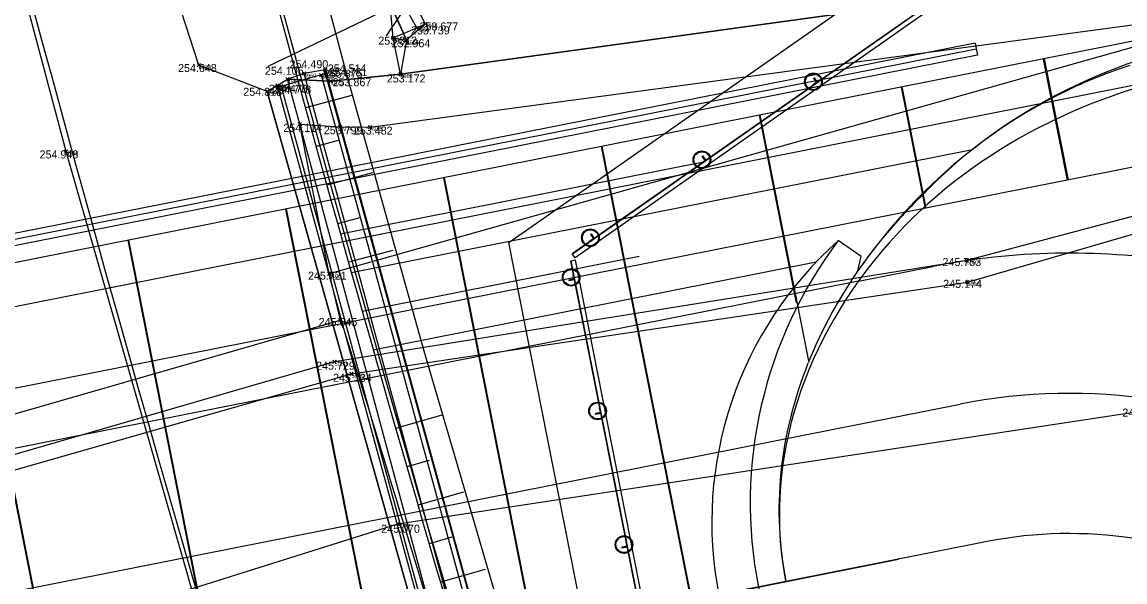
# Model space of a CAD drawing. Extents: x -809973 to -809318, y -1011363 to -1010505.
# Drawn here: x -809841.74 to -809827.96, y -1010985.79 to -1010978.8 of the extents above; entities that cross this region are included whole.
import ezdxf

# ---------------------------------------------------------------- set-up
doc = ezdxf.new("R2010")
doc.units = 0
for name, color, linetype in [('18b - zaměření - čísla bodů', 7, 'Continuous'), ('18c - zaměření - výšky', 7, 'Continuous'), ('Návrh', 7, 'Continuous'), ('SO04 - Železniční spodek', 7, 'Continuous'), ('SO_01', 7, 'Continuous'), ('stav_stav', 7, 'Continuous')]:
    doc.layers.add(name, color=color, linetype=linetype)

# ---------------------------------------------------------------- blocks, each defined once
blk = doc.blocks.new('POINT_DISPLAY')
for p, q in [((-0.021, -0.021), (0.021, 0.021)), ((-0.021, 0.021), (0.021, -0.021))]:
    blk.add_line(p, q)

msp = doc.modelspace()

# ---------------------------------------------------------------- linework, layer by layer
at = {"layer": 'Návrh'}
msp.add_arc((-809483.868, -1010882.207), 370.5, 195.00213, 204.78693, dxfattribs=at)
at = {"layer": 'SO04 - Železniční spodek'}
for points in [[(-809844.502, -1010948.259), (-809843.86, -1010951.753), (-809843.202, -1010955.243), (-809842.522, -1010958.729), (-809841.813, -1010962.21), (-809841.069, -1010965.683), (-809840.285, -1010969.148), (-809839.459, -1010972.604), (-809838.59, -1010976.05), (-809837.678, -1010979.484), (-809836.721, -1010982.905), (-809835.72, -1010986.314), (-809834.673, -1010989.708), (-809833.585, -1010993.088), (-809832.46, -1010996.457), (-809831.306, -1010999.816), (-809830.127, -1011003.167), (-809828.93, -1011006.512), (-809827.721, -1011009.854), (-809826.507, -1011013.193)], [(-809837.621, -1010979.718), (-809838.2, -1010979.874)], [(-809837.79, -1010980.282), (-809838.066, -1010980.356)], [(-809837.364, -1010980.685), (-809837.933, -1010980.837)], [(-809837.522, -1010981.245), (-809837.798, -1010981.319)], [(-809837.107, -1010981.651), (-809837.663, -1010981.8)], [(-809836.497, -1010983.709), (-809837.073, -1010983.873)], [(-809836.654, -1010984.273), (-809836.934, -1010984.353)], [(-809836.225, -1010984.671), (-809836.795, -1010984.833)], [(-809836.371, -1010985.233), (-809836.655, -1010985.313)], [(-809835.954, -1010985.634), (-809836.514, -1010985.793)]]:
    msp.add_lwpolyline(points, dxfattribs=at)
for centre, radius, start, end in [((-809453.305, -1010872.818), 406.4, 193.63597, 201.43276), ((-809483.922, -1010882.181), 367.5, 195.00277, 200.92799), ((-809524.411, -1010895.31), 331.2, 194.62152, 202.36706)]:
    msp.add_arc(centre, radius, start, end, dxfattribs=at)
at = {"layer": 'SO_01'}
for p, q in [((-809828.802, -1010977.453), (-809834.866, -1010981.695)), ((-809828.8, -1010977.457), (-809834.863, -1010981.699)), ((-809828.768, -1010977.502), (-809834.832, -1010981.744)), ((-809827.206, -1010978.912), (-809853.624, -1010984.137)), ((-809829.834, -1010979.065), (-809852.149, -1010983.48)), ((-809829.819, -1010979.139), (-809852.135, -1010983.553)), ((-809829.834, -1010979.065), (-809829.804, -1010979.213)), ((-809829.804, -1010979.213), (-809852.12, -1010983.627)), ((-809828.982, -1010979.263), (-809828.683, -1010980.774)), ((-809828.972, -1010979.261), (-809828.673, -1010980.772)), ((-809827.101, -1010979.442), (-809853.52, -1010984.667)), ((-809830.757, -1010979.614), (-809830.459, -1010981.125)), ((-809830.748, -1010979.612), (-809830.449, -1010981.123)), ((-809832.533, -1010979.965), (-809832.07, -1010982.305)), ((-809832.523, -1010979.964), (-809831.912, -1010983.053)), ((-809837.627, -1010981.926), (-809829.865, -1010980.391)), ((-809834.505, -1010980.356), (-809832.262, -1010991.694)), ((-809834.495, -1010980.354), (-809832.252, -1010991.692)), ((-809826.907, -1010980.423), (-809853.326, -1010985.648)), ((-809837.763, -1010981.443), (-809833.207, -1010980.542)), ((-809836.477, -1010980.746), (-809834.234, -1010992.084)), ((-809836.467, -1010980.744), (-809834.224, -1010992.082)), ((-809838.448, -1010981.136), (-809836.206, -1010992.474)), ((-809838.439, -1010981.134), (-809836.196, -1010992.472)), ((-809840.42, -1010981.526), (-809838.178, -1010992.864)), ((-809840.41, -1010981.524), (-809838.168, -1010992.862)), ((-809837.491, -1010982.409), (-809834.031, -1010981.724)), ((-809834.826, -1010981.774), (-809834.885, -1010981.785)), ((-809833.153, -1010990.515), (-809834.88, -1010981.784)), ((-809834.832, -1010981.744), (-809834.866, -1010981.695)), ((-809833.099, -1010990.504), (-809834.826, -1010981.774)), ((-809842.392, -1010981.916), (-809840.149, -1010993.254)), ((-809842.382, -1010981.914), (-809840.14, -1010993.252)), ((-809837.354, -1010982.891), (-809831.819, -1010981.796)), ((-809833.158, -1010990.516), (-809834.885, -1010981.785)), ((-809831.291, -1010982.037), (-809848.657, -1010985.472)), ((-809830.791, -1010985.512), (-809846.92, -1010988.702)), ((-809832.198, -1010985.784), (-809846.393, -1010988.591))]:
    msp.add_line(p, q, dxfattribs=at)
for points in [[(-809835.659, -1010981.554), (-809829.119, -1010976.981), (-809826.574, -1010976.477), (-809826.434, -1010978.736)], [(-809831.806, -1010979.554), (-809831.863, -1010979.594), (-809831.864, -1010979.592)], [(-809831.863, -1010979.586), (-809831.823, -1010979.558)], [(-809831.82, -1010979.545), (-809831.849, -1010979.504)], [(-809831.848, -1010979.498), (-809831.846, -1010979.497), (-809831.806, -1010979.554)], [(-809833.199, -1010980.529), (-809833.256, -1010980.569), (-809833.257, -1010980.567)], [(-809833.256, -1010980.56), (-809833.216, -1010980.532)], [(-809833.213, -1010980.519), (-809833.242, -1010980.479)], [(-809833.241, -1010980.473), (-809833.239, -1010980.471), (-809833.199, -1010980.529)], [(-809834.592, -1010981.503), (-809834.649, -1010981.543), (-809834.65, -1010981.541)], [(-809834.649, -1010981.535), (-809834.609, -1010981.506)], [(-809834.606, -1010981.494), (-809834.635, -1010981.453)], [(-809834.634, -1010981.447), (-809834.632, -1010981.446), (-809834.592, -1010981.503)], [(-809824.741, -1010990.164), (-809824.472, -1010992.461), (-809826.009, -1010992.763), (-809833.786, -1010991.025), (-809835.659, -1010981.554)], [(-809831.298, -1010981.906), (-809831.257, -1010981.729), (-809831.544, -1010981.53)], [(-809831.291, -1010982.037), (-809830.362, -1010981.853)], [(-809834.908, -1010982.027), (-809834.908, -1010982.029), (-809834.839, -1010982.016)], [(-809834.856, -1010982.012), (-809834.905, -1010982.022)], [(-809834.859, -1010981.953), (-809834.849, -1010982.001)], [(-809834.839, -1010982.016), (-809834.853, -1010981.947), (-809834.855, -1010981.948)], [(-809854.161, -1010988.344), (-809830.022, -1010983.57)], [(-809834.578, -1010983.695), (-809834.578, -1010983.697), (-809834.509, -1010983.684)], [(-809834.526, -1010983.68), (-809834.575, -1010983.689)], [(-809834.529, -1010983.621), (-809834.519, -1010983.669)], [(-809834.509, -1010983.684), (-809834.523, -1010983.615), (-809834.525, -1010983.615)], [(-809834.248, -1010985.362), (-809834.248, -1010985.365), (-809834.179, -1010985.351)], [(-809834.196, -1010985.347), (-809834.245, -1010985.357)], [(-809834.199, -1010985.288), (-809834.189, -1010985.337)], [(-809834.179, -1010985.351), (-809834.193, -1010985.283), (-809834.195, -1010985.283)], [(-809829.683, -1010985.286), (-809832.198, -1010985.784)]]:
    msp.add_lwpolyline(points, dxfattribs=at)
for centre, radius in [((-809831.854, -1010979.546), 0.11), ((-809831.854, -1010979.546), 0.1), ((-809833.247, -1010980.52), 0.11), ((-809833.247, -1010980.52), 0.1), ((-809834.64, -1010981.494), 0.11), ((-809834.64, -1010981.494), 0.1), ((-809834.88, -1010981.988), 0.11), ((-809834.88, -1010981.988), 0.1), ((-809834.55, -1010983.656), 0.11), ((-809834.55, -1010983.656), 0.1), ((-809834.22, -1010985.324), 0.11), ((-809834.22, -1010985.324), 0.1)]:
    msp.add_circle(centre, radius, dxfattribs=at)
for centre, radius, start, end in [((-809483.868, -1010882.207), 367.5, 195.00213, 200.05975), ((-809483.868, -1010882.207), 373.7, 195.00213, 199.87467), ((-809825.612, -1010985.836), 6.911, 103.0166, 145.3525), ((-809831.845, -1010979.502), 0.0045, 124.9748, 214.9749), ((-809831.828, -1010979.55), 0.009, 304.9748, 34.9749), ((-809831.861, -1010979.59), 0.0045, 124.9748, 214.9749), ((-809833.238, -1010980.476), 0.0045, 124.9748, 214.9749), ((-809833.221, -1010980.525), 0.009, 304.9748, 34.9749), ((-809833.254, -1010980.564), 0.0045, 124.9748, 214.9749), ((-809834.631, -1010981.451), 0.0045, 124.9748, 214.9749), ((-809834.614, -1010981.499), 0.009, 304.9748, 34.9749), ((-809834.647, -1010981.539), 0.0045, 124.9748, 214.9749), ((-809828.427, -1010985.044), 4.696, 131.5786, 250.7932), ((-809827.218, -1010984.804), 5.425, 142.8795, 239.4973), ((-809828.664, -1010990.436), 8.75, 81.0586, 101.1885), ((-809834.904, -1010982.026), 0.0045, 101.1885, 191.1886), ((-809834.854, -1010981.952), 0.0045, 101.1885, 191.1886), ((-809834.858, -1010982.003), 0.009, 281.1885, 11.1886), ((-809828.664, -1010990.436), 7, 81.0586, 101.1885), ((-809834.574, -1010983.694), 0.0045, 101.1885, 191.1886), ((-809834.524, -1010983.62), 0.0045, 101.1885, 191.1886), ((-809834.528, -1010983.671), 0.009, 281.1885, 11.1886), ((-809828.664, -1010990.436), 5.25, 81.0586, 101.1885), ((-809834.244, -1010985.361), 0.0045, 101.1885, 191.1886), ((-809834.194, -1010985.287), 0.0045, 101.1885, 191.1886), ((-809834.198, -1010985.339), 0.009, 281.1885, 11.1886)]:
    msp.add_arc(centre, radius, start, end, dxfattribs=at)
for centre, major_axis, ratio, start_param, end_param in [((-809826.127, -1010984.193), (-5.947, -1.176), 0.8, 4.717975, 5.497787), ((-809826.13, -1010984.193), (-5.722, -1.132), 0.882873, 4.848896, 5.031621), ((-809826.13, -1010984.193), (-5.722, -1.132), 0.882873, 5.033427, 5.386405), ((-809825.759, -1010984.12), (-6.315, -1.249), 0.8, 5.388601, 5.497787), ((-809825.207, -1010984.407), (-6.99, -1.383), 0.8, 5.497787, 5.801717), ((-809825.575, -1010984.48), (-6.622, -1.31), 0.8, 5.497787, 6.283185), ((-809825.207, -1010984.408), (-6.99, -1.383), 0.800068, 5.804756, 6.283146)]:
    msp.add_ellipse(centre, major_axis=major_axis, ratio=ratio, start_param=start_param, end_param=end_param, dxfattribs=at)
at = {"layer": 'stav_stav'}
for p, q in [((-809841.189, -1010980.417), (-809842.723, -1010974.633)), ((-809836.936, -1010979.029), (-809838.163, -1010976.258)), ((-809838.163, -1010976.258), (-809836.936, -1010979.029)), ((-809836.702, -1010978.825), (-809837.958, -1010976.205)), ((-809839.533, -1010979.34), (-809840.375, -1010976.742)), ((-809825.985, -1010977.935), (-809837.013, -1010979.451)), ((-809837.013, -1010979.451), (-809825.985, -1010977.935)), ((-809837.103, -1010978.997), (-809837.176, -1010978.22)), ((-809836.807, -1010978.875), (-809837.176, -1010978.22)), ((-809837.103, -1010978.997), (-809837.176, -1010978.22)), ((-809838.667, -1010979.352), (-809836.864, -1010978.487)), ((-809825.969, -1010978.581), (-809837.905, -1010981.945)), ((-809837.39, -1010980.112), (-809825.969, -1010978.581)), ((-809837.103, -1010978.997), (-809836.807, -1010978.875)), ((-809836.702, -1010978.825), (-809836.936, -1010979.029)), ((-809836.807, -1010978.875), (-809836.702, -1010978.825)), ((-809837.103, -1010978.997), (-809836.936, -1010979.029)), ((-809837.013, -1010979.451), (-809837.103, -1010978.997)), ((-809836.936, -1010979.029), (-809837.013, -1010979.451)), ((-809820.132, -1010979.173), (-809829.939, -1010981.776)), ((-809829.93, -1010982.048), (-809820.14, -1010979.21)), ((-809838.678, -1010979.669), (-809839.533, -1010979.34)), ((-809837.954, -1010979.399), (-809838.217, -1010979.445)), ((-809837.949, -1010979.444), (-809837.954, -1010979.399)), ((-809837.954, -1010979.399), (-809833.471, -1010995.68)), ((-809838.678, -1010979.669), (-809838.423, -1010979.516)), ((-809838.678, -1010979.669), (-809838.423, -1010979.516)), ((-809837.949, -1010979.444), (-809838.503, -1010979.604)), ((-809838.217, -1010979.445), (-809838.423, -1010979.516)), ((-809838.271, -1010980.078), (-809838.423, -1010979.516)), ((-809837.883, -1010979.54), (-809838.423, -1010979.516)), ((-809838.423, -1010979.516), (-809837.883, -1010979.54)), ((-809833.765, -1010995.721), (-809838.217, -1010979.445)), ((-809833.556, -1010995.643), (-809838.001, -1010979.464)), ((-809833.471, -1010995.68), (-809837.949, -1010979.444)), ((-809837.013, -1010979.451), (-809837.883, -1010979.54)), ((-809837.883, -1010979.54), (-809837.013, -1010979.451)), ((-809838.547, -1010979.594), (-809838.678, -1010979.669)), ((-809834.105, -1010995.845), (-809838.678, -1010979.669)), ((-809838.678, -1010979.669), (-809834.105, -1010995.845)), ((-809834.105, -1010995.845), (-809838.547, -1010979.594)), ((-809838.503, -1010979.604), (-809838.547, -1010979.594)), ((-809838.503, -1010979.604), (-809834.099, -1010995.814)), ((-809834.189, -1010995.204), (-809838.271, -1010980.078)), ((-809838.271, -1010980.078), (-809837.765, -1010980.109)), ((-809837.905, -1010981.945), (-809838.271, -1010980.078)), ((-809837.765, -1010980.109), (-809837.39, -1010980.112)), ((-809838.541, -1010989.632), (-809841.189, -1010980.417)), ((-809829.939, -1010981.776), (-809837.836, -1010983.041)), ((-809837.905, -1010981.945), (-809837.764, -1010982.524)), ((-809837.625, -1010983.192), (-809829.93, -1010982.048)), ((-809842.705, -1010983.942), (-809837.764, -1010982.524)), ((-809837.836, -1010983.041), (-809842.641, -1010984.432)), ((-809842.555, -1010984.599), (-809837.625, -1010983.192)), ((-809837.047, -1010985.065), (-809827.686, -1010983.646)), ((-809846.095, -1010987.906), (-809837.047, -1010985.065))]:
    msp.add_line(p, q, dxfattribs=at)
msp.add_lwpolyline([(-809837.185, -1010978.974), (-809836.864, -1010978.487), (-809837.444, -1010978.433)], dxfattribs=at)
for centre, major_axis, ratio, start_param, end_param in [((-809836.165, -1010987.823), (-1.604, 5.327), 0.005158, 3.151232, 6.385341), ((-809841.093, -1010989.234), (-1.62, 5.315), 0.003059, 6.189212, 9.436189)]:
    msp.add_ellipse(centre, major_axis=major_axis, ratio=ratio, start_param=start_param, end_param=end_param, dxfattribs=at)

# ---------------------------------------------------------------- block references
at = {"layer": '18b - zaměření - čísla bodů'}
for p in [(-809836.807, -1010978.875), (-809836.702, -1010978.825), (-809837.103, -1010978.997), (-809836.936, -1010979.029), (-809839.533, -1010979.34), (-809838.217, -1010979.445), (-809837.954, -1010979.399), (-809837.949, -1010979.444), (-809837.013, -1010979.451), (-809838.547, -1010979.594), (-809838.423, -1010979.516), (-809838.001, -1010979.464), (-809837.883, -1010979.54), (-809838.678, -1010979.669), (-809838.503, -1010979.604), (-809838.271, -1010980.078), (-809837.765, -1010980.109), (-809837.39, -1010980.112), (-809841.189, -1010980.417), (-809829.939, -1010981.776), (-809837.905, -1010981.945), (-809829.93, -1010982.048), (-809837.764, -1010982.524), (-809837.836, -1010983.041), (-809837.625, -1010983.192), (-809837.047, -1010985.065)]:
    msp.add_blockref('POINT_DISPLAY', p, dxfattribs=at)

# ---------------------------------------------------------------- texts
for s, p in [('4964', (-809836.807, -1010978.925)), ('4965', (-809836.702, -1010978.875)), ('4963', (-809837.103, -1010979.047)), ('4966', (-809836.936, -1010979.079)), ('4958', (-809839.533, -1010979.39)), ('4959', (-809837.954, -1010979.449)), ('4961', (-809838.423, -1010979.566)), ('4960', (-809838.217, -1010979.495)), ('4953', (-809838.001, -1010979.514)), ('4954', (-809837.949, -1010979.494)), ('4973', (-809837.883, -1010979.59)), ('4962', (-809837.013, -1010979.501)), ('4957', (-809838.678, -1010979.719)), ('4956', (-809838.547, -1010979.644)), ('4955', (-809838.503, -1010979.654)), ('4', (-809838.271, -1010980.128)), ('4974', (-809837.765, -1010980.159)), ('4975', (-809837.39, -1010980.162)), ('4906', (-809841.189, -1010980.467)), ('5097', (-809829.939, -1010981.826)), ('5108', (-809837.905, -1010981.995)), ('5096', (-809829.93, -1010982.098)), ('5109', (-809837.764, -1010982.574)), ('5080', (-809837.836, -1010983.091)), ('5079', (-809837.625, -1010983.242)), ('5078', (-809837.047, -1010985.115))]:
    msp.add_text(s, height=0.05, dxfattribs=at).set_placement(p)
at = {"layer": '18c - zaměření - výšky'}
for s, p in [('253.739', (-809836.881, -1010978.956)), ('253.677', (-809836.775, -1010978.906)), ('253.312', (-809837.29, -1010979.084)), ('252.964', (-809837.123, -1010979.116)), ('254.490', (-809838.398, -1010979.378)), ('254.648', (-809839.791, -1010979.425)), ('254.106', (-809838.706, -1010979.46)), ('255.875', (-809837.969, -1010979.496)), ('254.514', (-809837.921, -1010979.431)), ('254.781', (-809837.909, -1010979.476)), ('253.867', (-809837.86, -1010979.603)), ('253.172', (-809837.183, -1010979.556)), ('254.318', (-809838.976, -1010979.722)), ('254.475', (-809838.655, -1010979.684)), ('254.778', (-809838.611, -1010979.694)), ('254.114', (-809838.476, -1010980.172)), ('253.799', (-809837.97, -1010980.203)), ('253.482', (-809837.594, -1010980.206)), ('254.948', (-809841.521, -1010980.504)), ('245.753', (-809830.241, -1010981.847)), ('245.721', (-809838.168, -1010982.017)), ('245.174', (-809830.232, -1010982.119)), ('245.645', (-809838.035, -1010982.596)), ('245.729', (-809838.066, -1010983.141)), ('245.134', (-809837.855, -1010983.292)), ('245.152', (-809827.994, -1010983.726)), ('245.070', (-809837.253, -1010985.176))]:
    msp.add_text(s, height=0.1, dxfattribs=at).set_placement(p)

doc.saveas('drawing.dxf')
